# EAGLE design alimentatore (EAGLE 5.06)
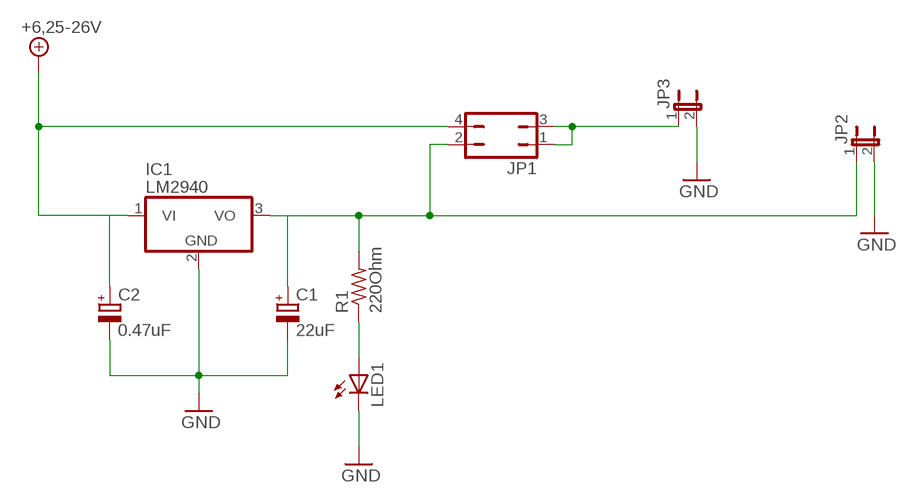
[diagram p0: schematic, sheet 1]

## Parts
C1  22uF  CPOL-EUE2-5  [E2-5]
C2  0.47uF  CPOL-EUE2-5  [E2-5]
IC1  LM2940  7805TV  [TO220V]
JP1  JP2Q  [JP2Q]
JP2  JP1E  [JP1]
JP3  JP1E  [JP1]
LED1  LED5MM  [LED5MM]
R1  220Ohm  R-US_0207/10  [0207/10]

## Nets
+12V: C2.+ IC1.1(VI) JP1.4 ; supply symbol labelled +6,25-26V
GND: C1.- C2.- IC1.2(GND) JP2.2 JP3.2 LED1.K(C)
N$1: JP1.1 JP1.3 JP3.1
N$2: C1.+ IC1.3(VO) JP1.2 JP2.1 R1.2
N$4: LED1.A R1.1

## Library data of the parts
C1 C2 = rcl:CPOL-EU: POLARIZED CAPACITOR, European symbol
IC1 = linear:78*: Positive VOLTAGE REGULATOR Source: http://cache.national.com/ds/LM/LM78L05.pdf http://www.fairchildsemi.com/ds/LM/LM7805.pdf
JP1 = jumper:JP2Q: JUMPER
JP2 JP3 = jumper:JP1E: JUMPER
LED1 = led:LED: LED
R1 = resistor:R-US_: RESISTOR, American symbol

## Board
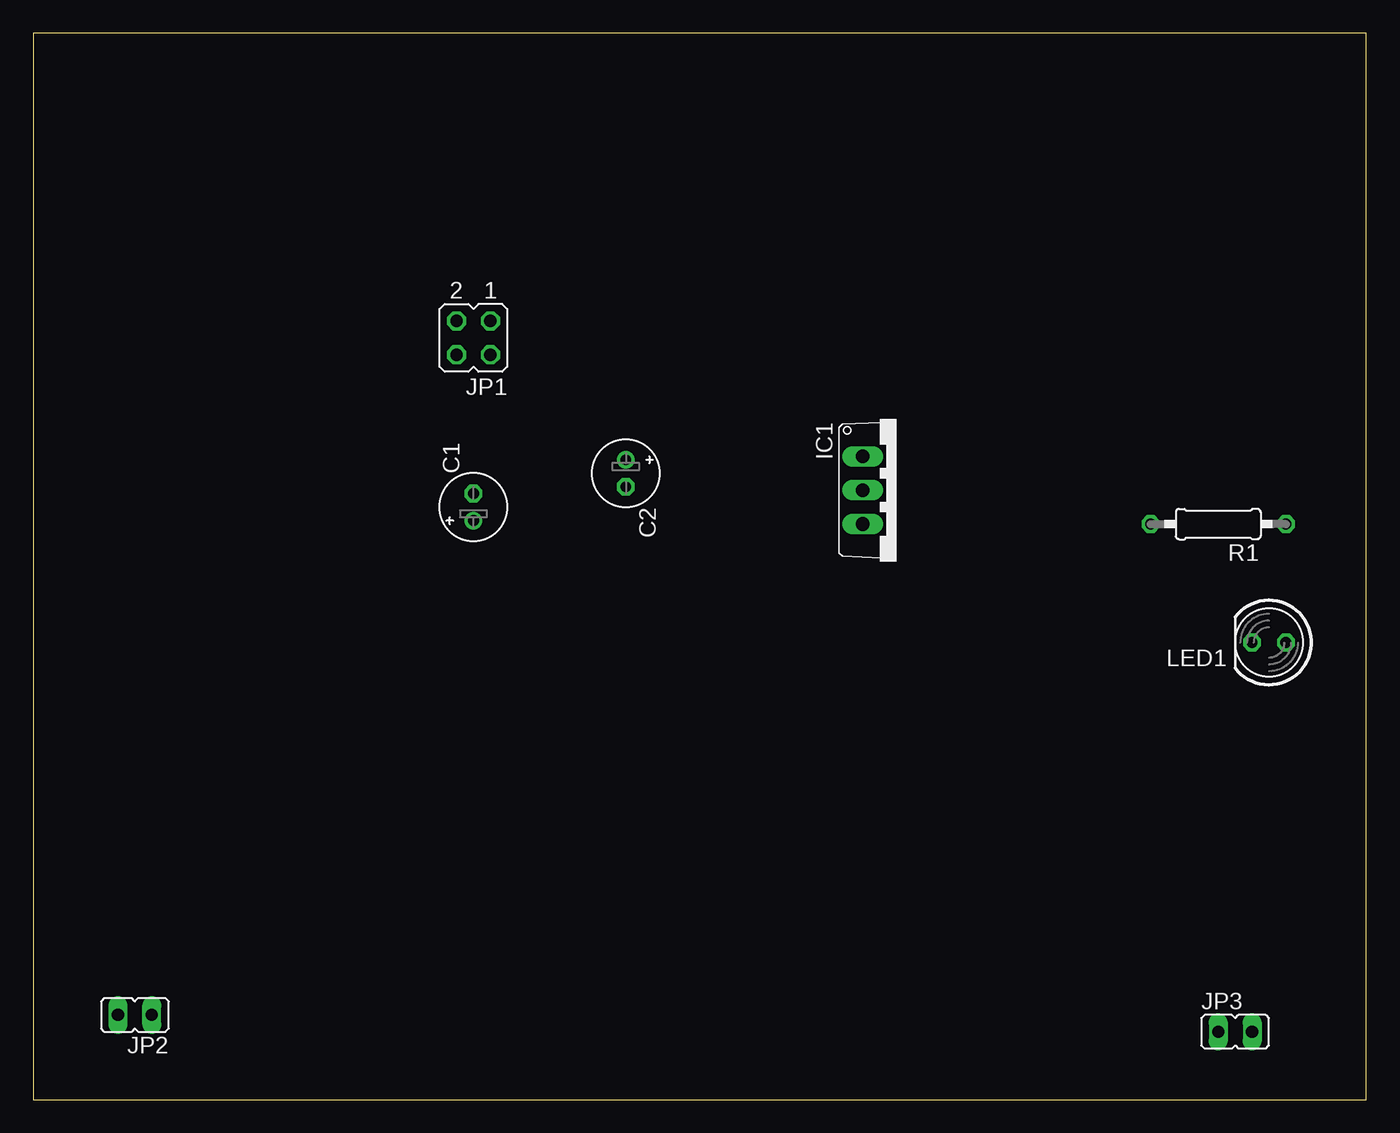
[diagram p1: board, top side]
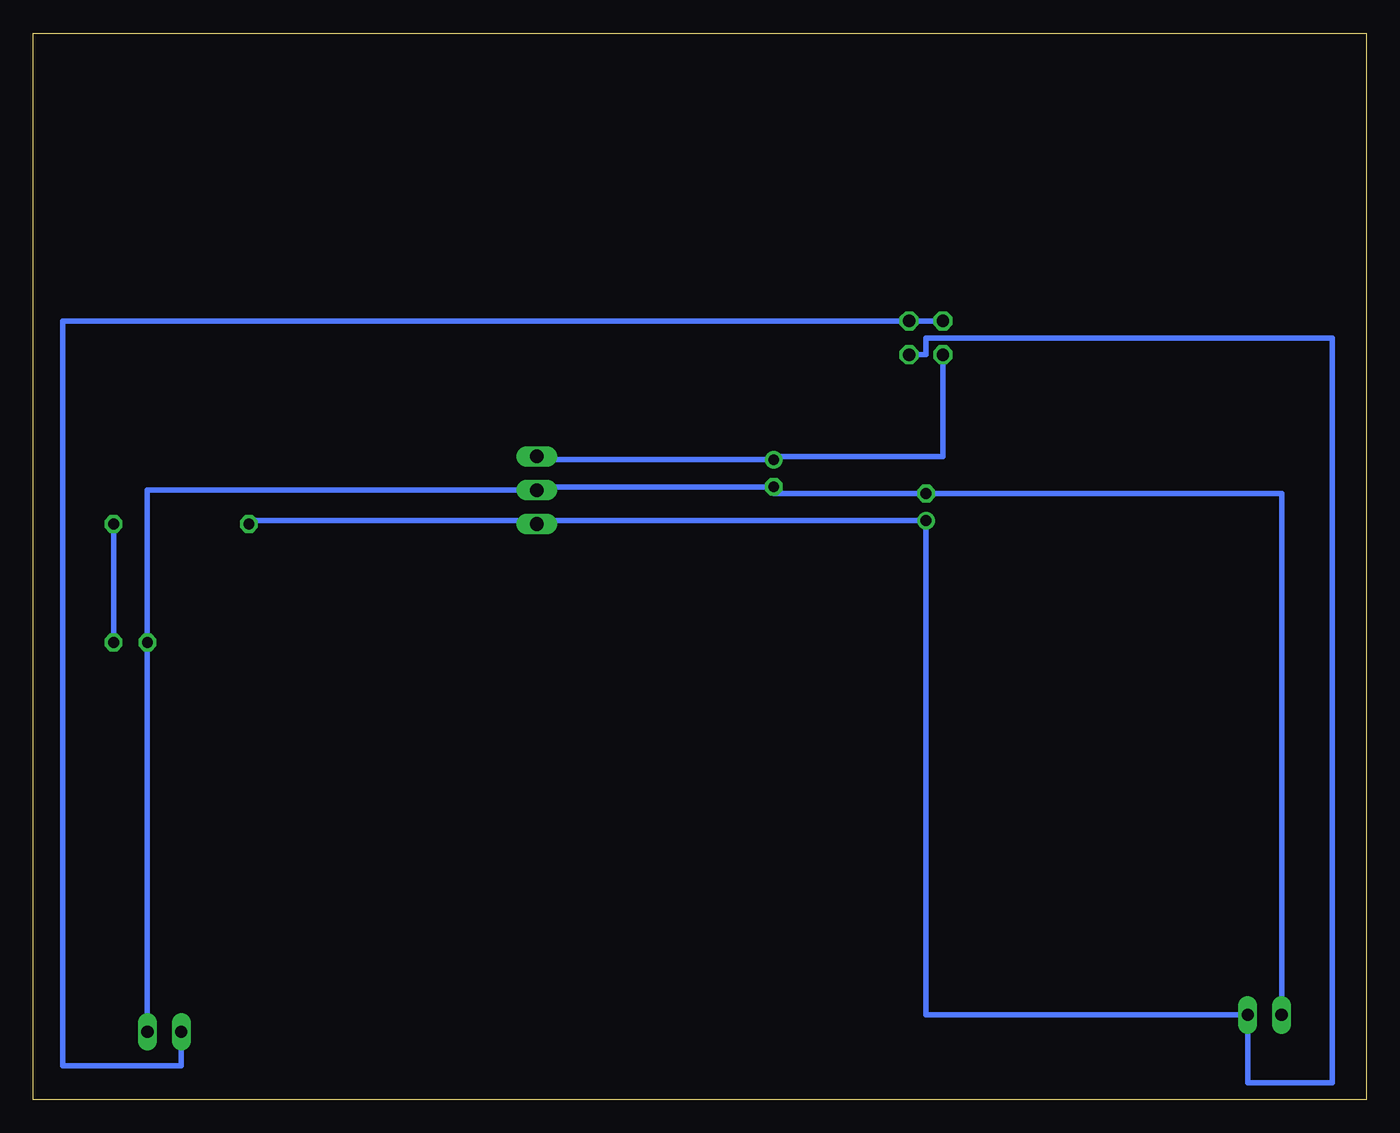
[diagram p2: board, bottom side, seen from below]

Size 100 x 80 mm. Coordinates in mm from the lower left corner, seen from the top.
Outline: 0,0 100,0 100,80 0,80 0,0
Copper layers (1*16): Top 0.035mm / dielectric 1.5mm / Bottom 0.035mm
Design rules "default": minimum track width 10mil, minimum drill 24mil, track to track 8mil, track to pad 8mil, pad to pad 8mil, via to via 8mil, smd to smd 8mil, copper to edge 40mil, drill to drill 8mil, minimum pad ring 10mil, minimum via ring 8mil, stop-mask expansion 4mil, vias tented up to drill 0mil, thermal gap 10mil

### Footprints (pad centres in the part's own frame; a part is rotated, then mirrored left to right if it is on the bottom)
E2-5 = drill 0.813 pad 1.27 round: + -1.016,0 | drill 0.813 pad 1.27 octagon: - 1.016,0
TO220V = drill 1.016 long: 1 -2.54,-2.54; 2 0,-2.54; 3 2.54,-2.54
JP2Q = drill 0.914 octagon: 1 -1.27,-1.27; 2 -1.27,1.27; 3 1.27,-1.27; 4 1.27,1.27
JP1 = drill 0.914 long: 1 0,-1.27; 2 0,1.27
LED5MM = drill 0.813 octagon: A -1.27,0; K 1.27,0
0207/10 = drill 0.813 octagon: 1 -5.08,0; 2 5.08,0

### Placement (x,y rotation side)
C1  33.02,44.45 90 top
C2  44.45,46.99 270 top
IC1  64.77,45.72 270 top
JP1  33.02,57.15 180 top
JP2  7.62,6.35 90 top
JP3  90.17,5.08 270 top
LED1  92.71,34.29 180 top
R1  88.9,43.18 180 top

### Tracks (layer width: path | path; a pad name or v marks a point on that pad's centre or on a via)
+12V
  Bottom 0.406: IC1.1 62.23,48.01 C2.+ 44.45,48.26 31.75,48.26 JP1.4
GND
  Bottom 0.406: JP2.2 6.35,45.47 C1.- 44.45,45.47 C2.- 62.23,45.97 IC1.2 91.44,45.72 LED1.K JP3.2
N$1
  Bottom 0.406: JP1.3 JP1.1 97.79,58.42 97.79,2.54 88.9,2.54 JP3.1
N$2
  Bottom 0.406: 62.23,43.43 C1.+ 33.02,6.35 JP2.1 8.89,1.27 2.54,1.27 2.54,57.15 33.02,57.15 33.02,55.88 JP1.2 | 62.23,43.43 IC1.3 | 62.23,43.43 83.82,43.43 R1.2
N$4
  Bottom 0.406: R1.1 LED1.A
